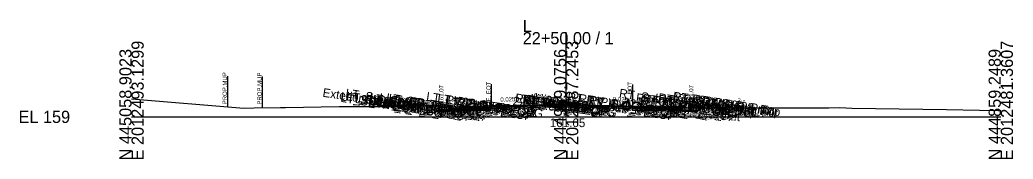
# Model space of a CAD drawing. Extents: x -26 to 4203, y -10 to 9526.
# Drawn here: x 974.3 to 1202.8, y 2490.3 to 2522.3 of the extents above; entities that cross this region are included whole.
import ezdxf

# ---------------------------------------------------------------- set-up
doc = ezdxf.new("R2010")
doc.units = 0
for name, color, linetype in [('Default', 7, 'Continuous'), ('Exist CMT Pavement', 7, 'Continuous'), ('Exist Cross Section Cell', 7, 'Continuous'), ('Exist XS Center Line Elevation Label', 7, 'Continuous'), ('Exist XS Ground Line', 7, 'Continuous'), ('Prop CMT Conc Surface', 7, 'Continuous'), ('Prop CMT Concrete Structures', 7, 'Continuous'), ('Prop CMT Pvmt Course 1', 7, 'Continuous'), ('Prop CMT Pvmt Course 1 CG', 7, 'Continuous'), ('Prop CMT Pvmt Course 1 Wedge', 7, 'Continuous'), ('Prop CMT Pvmt Course 2', 7, 'Continuous'), ('Prop CMT Pvmt Course 3', 7, 'Continuous'), ('Prop CMT Pvmt Surface', 7, 'Continuous'), ('Prop CMT Pvmt Wedge Surface 1', 7, 'Continuous'), ('Prop CMT Pvmt Wedge Surface 2', 7, 'Continuous'), ('Prop CMT Pvmt Wedge Surface 3', 7, 'Continuous'), ('Prop CMT Slope Grass', 7, 'Continuous'), ('Prop CMT Subgrade Earthwork', 7, 'Continuous'), ('Prop XS Hydro Elevations', 7, 'Continuous'), ('Prop XS Label Text', 7, 'Continuous'), ('Prop XS SE Text', 7, 'Continuous'), ('Prop XS Side Slope Text', 7, 'Continuous'), ('Scratch_Level_0', 7, 'Continuous')]:
    doc.layers.add(name, color=color, linetype=linetype)

msp = doc.modelspace()

# ---------------------------------------------------------------- linework, layer by layer
at = {"layer": 'Exist CMT Pavement'}
for points in [[(1100, 2502.65), (1099.02, 2502.66), (1098.71, 2502.65), (1096.51, 2502.63), (1096.05, 2502.63), (1094.01, 2502.62), (1093.71, 2502.62), (1093.67, 2502.62), (1093.29, 2502.62), (1091.51, 2502.6), (1090.76, 2502.59), (1089.03, 2502.59), (1087.47, 2502.55), (1086.5, 2502.53), (1085.09, 2502.52), (1084, 2502.51), (1082.9, 2502.5), (1082.74, 2502.5)], [(1100, 2502.65), (1101.37, 2502.64), (1101.52, 2502.64), (1102.1, 2502.64), (1103.8, 2502.64), (1104.02, 2502.64), (1104.15, 2502.64), (1106.32, 2502.6), (1106.5, 2502.59), (1106.66, 2502.59), (1109.01, 2502.58), (1111.1, 2502.52), (1111.51, 2502.51), (1111.98, 2502.51), (1114.03, 2502.48), (1114.43, 2502.48), (1115.26, 2502.46), (1115.27, 2502.46)]]:
    msp.add_lwpolyline(points, dxfattribs=at)
at = {"layer": 'Exist Cross Section Cell'}
for p, q in [((1100, 2500), (1100, 2519.47)), ((1000, 2500), (1100, 2500)), ((1100, 2500), (1200, 2500))]:
    msp.add_line(p, q, dxfattribs=at)
at = {"layer": 'Exist XS Ground Line'}
msp.add_lwpolyline([(1000, 2504.11), (1025.83, 2501.97), (1028.24, 2502.06), (1034.29, 2502.17), (1035.39, 2502.19), (1047.81, 2502.35), (1050.12, 2502.37), (1052.53, 2502.37), (1058.58, 2502.39), (1060.66, 2502.39), (1063.37, 2502.39), (1075.39, 2502.28), (1075.78, 2502.3), (1078.18, 2502.28), (1079.11, 2502.34), (1081.49, 2502.46), (1082.74, 2502.5), (1084, 2502.51), (1085.09, 2502.52), (1086.5, 2502.53), (1087.47, 2502.55), (1089.03, 2502.59), (1090.76, 2502.59), (1091.51, 2502.6), (1093.29, 2502.62), (1093.67, 2502.62), (1094.01, 2502.62), (1096.05, 2502.63), (1096.51, 2502.63), (1098.71, 2502.65), (1099.02, 2502.66), (1100, 2502.65), (1101.52, 2502.64), (1102.1, 2502.64), (1104.15, 2502.64), (1106.66, 2502.59), (1109.01, 2502.58), (1111.1, 2502.52), (1111.51, 2502.51), (1111.98, 2502.51), (1114.03, 2502.48), (1114.43, 2502.48), (1115.26, 2502.46), (1115.76, 2502.44), (1116.52, 2502.39), (1119.89, 2502.11), (1121.06, 2502.01), (1122.69, 2501.9), (1123.9, 2501.92), (1126.91, 2502.09), (1136.88, 2502.1), (1140.4, 2502.11), (1146.36, 2502.09), (1150.42, 2502.07), (1155.83, 2502.09), (1160.44, 2502.11), (1162.96, 2502.15), (1165.74, 2502.03), (1187.48, 2501.71), (1195.13, 2501.54), (1199.43, 2501.5), (1200, 2501.49)], dxfattribs=at)
at = {"layer": 'Prop CMT Conc Surface'}
for points in [[(1071.25, 2502.07), (1071.25, 2502.57), (1070.75, 2502.57)], [(1128.75, 2502.07), (1128.75, 2502.57), (1129.25, 2502.57)], [(1133.25, 2502.66), (1138.25, 2502.76)], [(1073.25, 2502.2), (1071.25, 2502.07)], [(1126.75, 2502.2), (1128.75, 2502.07)]]:
    msp.add_lwpolyline(points, dxfattribs=at)
at = {"layer": 'Prop CMT Concrete Structures'}
for points in [[(1073.25, 2502.2), (1071.25, 2502.07), (1071.25, 2502.57), (1070.75, 2502.57)], [(1070.75, 2502.57), (1070.75, 2501.55), (1073.25, 2501.61)], [(1102, 2502.82), (1101.99, 2502.98), (1101.24, 2503.23), (1100, 2503.26), (1098.76, 2503.23), (1098.01, 2502.98), (1098, 2502.82)], [(1098, 2502.82), (1100, 2502.87), (1102, 2502.82)], [(1126.75, 2502.2), (1128.75, 2502.07), (1128.75, 2502.57), (1129.25, 2502.57)], [(1129.25, 2502.57), (1129.25, 2501.55), (1126.75, 2501.61)], [(1138.25, 2502.76), (1133.25, 2502.66)], [(1133.25, 2502.66), (1133.25, 2502.32)], [(1138.25, 2502.42), (1138.25, 2502.76)], [(1073.25, 2501.61), (1073.25, 2502.2)], [(1126.75, 2501.61), (1126.75, 2502.2)], [(1133.25, 2502.32), (1138.25, 2502.42)]]:
    msp.add_lwpolyline(points, dxfattribs=at)
at = {"layer": 'Prop CMT Pvmt Course 1'}
for points in [[(1100, 2502.87), (1073.25, 2502.2)], [(1082.74, 2502.31), (1100, 2502.74)], [(1100, 2502.62), (1100, 2502.87)], [(1100, 2502.87), (1126.75, 2502.2)], [(1100, 2502.62), (1100, 2502.87)], [(1100, 2502.74), (1100, 2502.62), (1100, 2502.62)], [(1115.27, 2502.36), (1100, 2502.74)], [(1100, 2502.74), (1100, 2502.62), (1100, 2502.62)], [(1073.25, 2502.2), (1073.25, 2501.95)], [(1073.25, 2501.95), (1082.74, 2502.18)], [(1082.74, 2502.18), (1082.74, 2502.31)], [(1115.27, 2502.23), (1115.27, 2502.36)], [(1126.75, 2501.95), (1115.27, 2502.23)], [(1126.75, 2502.2), (1126.75, 2501.95)]]:
    msp.add_lwpolyline(points, dxfattribs=at)
at = {"layer": 'Prop CMT Pvmt Course 1 CG'}
for points in [[(1073.25, 2501.61), (1070.25, 2501.54), (1069.91, 2501.2)], [(1069.91, 2501.2), (1073.25, 2501.28)], [(1073.25, 2501.28), (1073.25, 2501.61)], [(1126.75, 2501.61), (1129.75, 2501.54), (1130.09, 2501.2)], [(1126.75, 2501.28), (1126.75, 2501.61)], [(1130.09, 2501.2), (1126.75, 2501.28)]]:
    msp.add_lwpolyline(points, dxfattribs=at)
at = {"layer": 'Prop CMT Pvmt Course 1 Wedge'}
for points in [[(1100, 2502.65), (1099.02, 2502.66), (1098.71, 2502.65), (1096.51, 2502.63), (1096.05, 2502.63), (1095.43, 2502.63)], [(1095.43, 2502.63), (1096.05, 2502.64)], [(1096.05, 2502.64), (1096.51, 2502.65), (1098.71, 2502.71), (1099.02, 2502.72), (1100, 2502.74)], [(1100, 2502.74), (1100, 2502.65)], [(1100, 2502.74), (1101.37, 2502.71), (1101.52, 2502.7), (1102.1, 2502.69), (1103.8, 2502.65), (1104, 2502.64)], [(1100, 2502.65), (1100, 2502.74)], [(1104, 2502.64), (1103.8, 2502.64), (1102.1, 2502.64), (1101.52, 2502.64), (1101.37, 2502.64), (1100, 2502.65)]]:
    msp.add_lwpolyline(points, dxfattribs=at)
at = {"layer": 'Prop CMT Pvmt Course 2'}
for points in [[(1082.74, 2502.18), (1073.25, 2501.95)], [(1073.25, 2501.95), (1073.25, 2501.61)], [(1073.25, 2501.61), (1082.74, 2501.85)], [(1082.74, 2501.85), (1082.74, 2502.18)], [(1115.27, 2501.9), (1115.27, 2502.23)], [(1115.27, 2502.23), (1126.75, 2501.95)], [(1126.75, 2501.61), (1115.27, 2501.9)], [(1126.75, 2501.95), (1126.75, 2501.61)]]:
    msp.add_lwpolyline(points, dxfattribs=at)
at = {"layer": 'Prop CMT Pvmt Course 3'}
for points in [[(1082.74, 2501.85), (1073.25, 2501.61)], [(1073.25, 2501.61), (1073.25, 2501.28)], [(1073.25, 2501.28), (1082.74, 2501.52)], [(1082.74, 2501.52), (1082.74, 2501.85)], [(1115.27, 2501.9), (1126.75, 2501.61)], [(1115.27, 2501.57), (1115.27, 2501.9)], [(1126.75, 2501.28), (1115.27, 2501.57)], [(1126.75, 2501.61), (1126.75, 2501.28)]]:
    msp.add_lwpolyline(points, dxfattribs=at)
at = {"layer": 'Prop CMT Pvmt Surface'}
for points in [[(1100, 2502.87), (1073.25, 2502.2)], [(1100, 2502.87), (1126.75, 2502.2)]]:
    msp.add_lwpolyline(points, dxfattribs=at)
at = {"layer": 'Prop CMT Pvmt Wedge Surface 1'}
for points in [[(1100, 2502.74), (1082.74, 2502.31)], [(1100, 2502.74), (1115.27, 2502.36)], [(1073.25, 2501.95), (1073.25, 2502.2)], [(1082.74, 2502.18), (1073.25, 2501.95)], [(1082.74, 2502.31), (1082.74, 2502.18)], [(1115.27, 2502.36), (1115.27, 2502.23)], [(1115.27, 2502.23), (1126.75, 2501.95)], [(1126.75, 2501.95), (1126.75, 2502.2)]]:
    msp.add_lwpolyline(points, dxfattribs=at)
at = {"layer": 'Prop CMT Pvmt Wedge Surface 2'}
for points in [[(1100, 2502.62), (1073.25, 2501.95)], [(1100, 2502.62), (1126.75, 2501.95)], [(1073.25, 2501.95), (1073.25, 2502.2)], [(1126.75, 2501.95), (1126.75, 2502.2)]]:
    msp.add_lwpolyline(points, dxfattribs=at)
at = {"layer": 'Prop CMT Pvmt Wedge Surface 3'}
for points in [[(1100, 2502.28), (1073.25, 2501.61)], [(1073.25, 2501.61), (1073.25, 2502.2)], [(1100, 2502.28), (1126.75, 2501.61)], [(1126.75, 2501.61), (1126.75, 2502.2)]]:
    msp.add_lwpolyline(points, dxfattribs=at)
at = {"layer": 'Prop CMT Slope Grass'}
for points in [[(1070.75, 2502.57), (1061.25, 2502.76), (1060.15, 2502.39)], [(1129.25, 2502.57), (1138.75, 2502.76), (1140.7, 2502.11)]]:
    msp.add_lwpolyline(points, dxfattribs=at)
at = {"layer": 'Prop CMT Subgrade Earthwork'}
for points in [[(1073.25, 2501.28), (1069.91, 2501.2), (1068.49, 2502.61)], [(1082.74, 2501.52), (1082.74, 2502.5)], [(1115.27, 2501.57), (1115.26, 2502.46)], [(1126.75, 2501.28), (1130.09, 2501.2), (1131.51, 2502.61)], [(1082.74, 2501.52), (1073.25, 2501.28)], [(1115.27, 2501.57), (1126.75, 2501.28)]]:
    msp.add_lwpolyline(points, dxfattribs=at)
at = {"layer": 'Prop XS Label Text'}
for p, q in [((1022.05, 2509.32), (1022.05, 2502.32)), ((1030.05, 2509.25), (1030.05, 2502.25)), ((1082.74, 2507.5), (1082.74, 2502.5)), ((1115.26, 2507.46), (1115.26, 2502.46))]:
    msp.add_line(p, q, dxfattribs=at)

# ---------------------------------------------------------------- texts
at = {"layer": 'Default'}
msp.add_text('-', height=0.0001, dxfattribs=at).set_placement((1000, 2500))
at = {"layer": 'Exist Cross Section Cell'}
for s, p in [('L', (1090, 2519.47)), ('22+50.00 / 1', (1090, 2516.67)), ('EL 159', (974, 2498.6))]:
    msp.add_text(s, height=2.8, dxfattribs=at).set_placement(p)
for s, p in [('E 2012493.1299', (1002.8, 2490)), ('E 2012487.2453', (1102.8, 2490)), ('E 2012481.3607', (1202.8, 2490)), ('N 445058.9023', (1000, 2490)), ('N 444959.0756', (1100, 2490)), ('N 444859.2489', (1200, 2490))]:
    msp.add_text(s, height=2.8, rotation=90, dxfattribs=at).set_placement(p)
at = {"layer": 'Exist XS Center Line Elevation Label'}
msp.add_text('161.65', height=2, dxfattribs=at).set_placement((1096.22, 2497.65))
at = {"layer": 'Prop XS Hydro Elevations'}
for p in [(1071.75, 2503.07), (1129.25, 2503.07)]:
    msp.add_text('161.07', height=1, rotation=90, dxfattribs=at).set_placement(p)
at = {"layer": 'Prop XS Label Text'}
for s, p in [('PROP.MUP', (1021.95, 2502.89)), ('PROP.MUP', (1029.95, 2502.82)), ('E. EOT', (1082.64, 2503.53)), ('E. EOT', (1115.16, 2503.48))]:
    msp.add_text(s, height=1, rotation=90, dxfattribs=at).set_placement(p)
at = {"layer": 'Prop XS SE Text'}
for rotation, p in [(1.4327, (1084.87, 2503.49)), (358.5674, (1110.74, 2503.59))]:
    msp.add_text('0.025', height=1, rotation=rotation, dxfattribs=at).set_placement(p)
at = {"layer": 'Prop XS Side Slope Text'}
for rotation, p in [(18.4382, (1059.24, 2502.87)), (341.5771, (1139.21, 2503.4))]:
    msp.add_text('3:1', height=1, rotation=rotation, dxfattribs=at).set_placement(p)
at = {"layer": 'Scratch_Level_0'}
for s, p in [('Exterior Boundary', (1043.87, 2504.64)), ('LT_SDWK_Out_Top', (1047.99, 2503.81)), ('LT_SDWK_Out_Bot', (1048.02, 2503.47)), ('LT_Sub_Trench_Out_DLT', (1049.13, 2504.51)), ('LT_Slope_Cut', (1049.3, 2503.82)), ('LT_CSLP_Pnt', (1051.38, 2503.23)), ('LT_SDWK_In_Top', (1054.59, 2503.47)), ('LT_SDWK_In_Bot', (1054.63, 2503.13)), ('LT_CG_Top_Face', (1058.5, 2503.47)), ('LT_CG_Top_BOC', (1059.01, 2503.32)), ('LT_CG_Top_Gut', (1059.47, 2502.82)), ('LT_PV_Sub_Tie_Out', (1067.72, 2503.75)), ('LT_PV_OEEOP_EG', (1070.27, 2503.36)), ('LT_PV2_OEEOP', (1072.02, 2502.78)), ('LT_PV1_OEEOP', (1072.58, 2502.82)), ('RT_PV_IEEOP_EG', (1088.12, 2503.42)), ('LT_PV_IEEOP_EG', (1088.17, 2503.41)), ('MI_Face In', (1089.84, 2503.2)), ('RT_PV2_IEEOP', (1089.87, 2503.12)), ('RT_PV3_IEEOP', (1089.87, 2502.79)), ('LT_PV2_IEEOP', (1089.92, 2503.12)), ('LT_PV3_IEEOP', (1089.92, 2502.78)), ('RT_PV1_IEEOP', (1090.43, 2503.17)), ('LT_PV1_IEEOP', (1090.48, 2503.16)), ('MI_Bot In', (1090.81, 2502.88)), ('22+50.00', (1091.17, 2502.84)), ('MI_Top In', (1091.54, 2503.3)), ('MI_Face Out', (1092.22, 2503.44)), ('MI_Top Out', (1092.42, 2503.54)), ('MI_Crown', (1093, 2503.3)), ('MI_Bot Out', (1093.21, 2503.12)), ('22+50.00', (1095.16, 2502.94)), ('RT_PV_Sub_Tie_Out', (1100.17, 2503.71)), ('RT_PV_OEEOP_EG', (1102.75, 2503.32)), ('RT_PV2_OEEOP', (1104.5, 2502.84)), ('RT_PV1_OEEOP', (1105.06, 2502.88)), ('RT_Sub_Trench_Out_DLT', (1112.09, 2504.51)), ('RT_CG_Top_Face', (1115.96, 2503.47)), ('RT_CG_Top_Gut', (1116.92, 2502.83)), ('RT_CG_Top_BOC', (1117.47, 2503.32)), ('RT_SDWK_In_Top', (1121.05, 2503.48)), ('RT_SDWK_In_Bot', (1121.08, 2503.14)), ('RT_SDWK_Out_Top', (1124.44, 2503.82)), ('RT_SDWK_Out_Bot', (1124.47, 2503.48)), ('Exterior Boundary', (1124.86, 2503.47)), ('RT_CSLP_Pnt', (1128.84, 2503.23)), ('22+50.00', (1054.8, 2502.77)), ('LT_CG1_Shelf_Out', (1056.8, 2502.54)), ('22+50.00', (1057.9, 2502.71)), ('LT_CG_Bot_BOC', (1059.05, 2502.3)), ('LT_Sub_OEOP', (1059.98, 2501.68)), ('22+50.00', (1060.26, 2502.66)), ('22+50.00', (1062.7, 2502.6)), ('LT_CG_Bot_IE', (1063.13, 2502.12)), ('LT_Sub_OEOT', (1063.29, 2501.76)), ('LT_PV2_OEOT', (1063.38, 2502.42)), ('LT_PV3_OEOT', (1063.38, 2502.08)), ('LT_PV1_OEOT', (1063.94, 2502.58)), ('22+50.00', (1064.27, 2502.58)), ('22+50.00', (1071.83, 2502.32)), ('LT_Sub_OEEOP', (1071.92, 2502.13)), ('LT_PV3_OEEOP', (1072.02, 2502.45)), ('22+50.00', (1073.57, 2502.42)), ('22+50.00', (1075.32, 2502.5)), ('22+50.00', (1075.91, 2502.52)), ('22+50.00', (1087.64, 2502.76)), ('PV2_PGL', (1093.82, 2502.53)), ('PV1_PGL', (1094.38, 2502.7)), ('MI_Bot', (1095.09, 2502.59)), ('RT_Sub_OEEOP', (1104.4, 2502.19)), ('RT_PV3_OEEOP', (1104.5, 2502.51)), ('22+50.00', (1113.01, 2502.38)), ('RT_CG1_Shelf_Out', (1116.26, 2502.55)), ('RT_CG_Bot_IE', (1116.58, 2502.13)), ('RT_Sub_OEOT', (1116.74, 2501.77)), ('RT_PV2_OEOT', (1116.84, 2502.42)), ('RT_PV3_OEOT', (1116.84, 2502.09)), ('RT_PV1_OEOT', (1117.4, 2502.59)), ('RT_CG_Bot_BOC', (1117.5, 2502.3)), ('RT_Sub_OEOP', (1120.12, 2501.68)), ('22+50.00', (1122.38, 2502.58)), ('22+50.00', (1122.74, 2502.59)), ('22+50.00', (1125.33, 2502.64)), ('22+50.00', (1128.67, 2502.72)), ('RT_Slope_Fill', (1131.13, 2502.53)), ('22+50.00', (1131.88, 2502.77))]:
    msp.add_text(s, height=2, rotation=351.4697, dxfattribs=at).set_placement(p)

doc.saveas('drawing.dxf')
